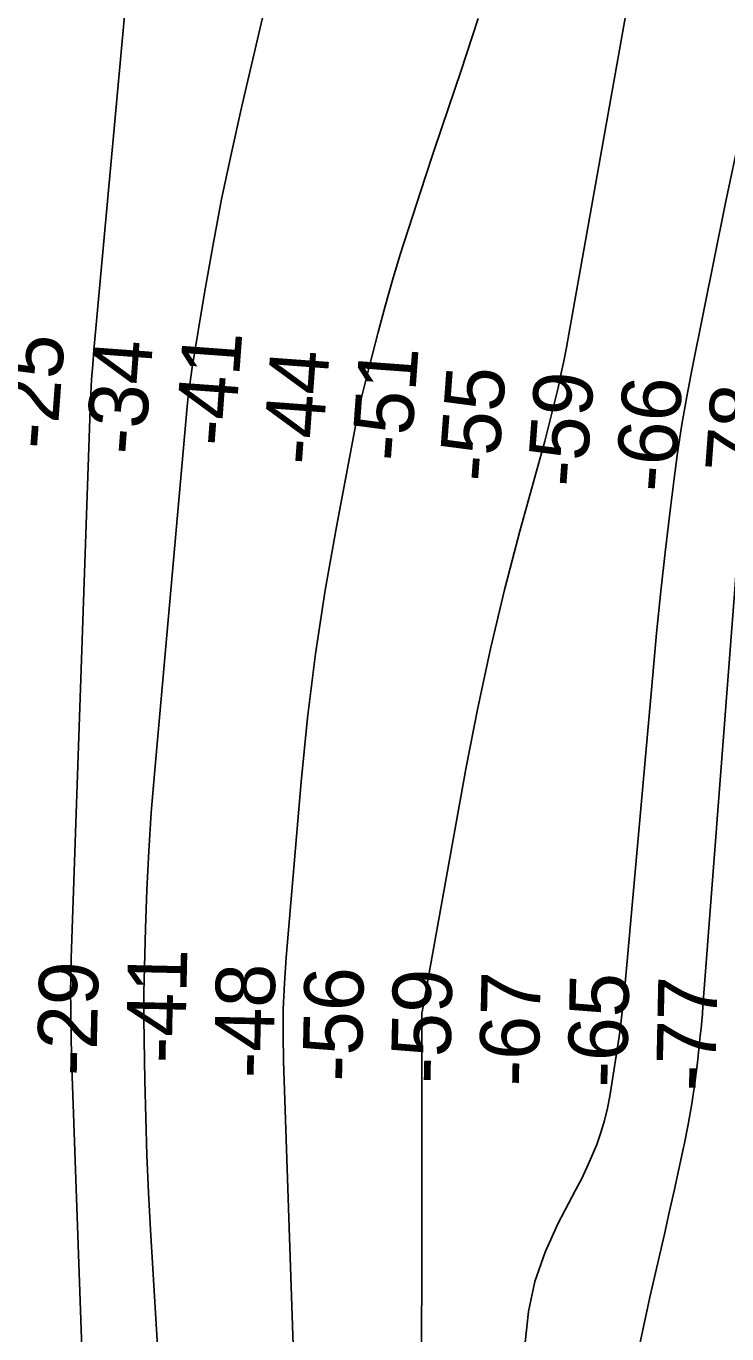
# Model space of a CAD drawing. Extents: x 3392644 to 3430565, y 576657 to 602123.
# Drawn here: x 3402367 to 3403159, y 590935 to 592413 of the extents above; entities that cross this region are included whole.
import ezdxf

# ---------------------------------------------------------------- set-up
doc = ezdxf.new("R2010")
doc.units = 0
for name, color, linetype in [('V-RIVR-EDGE', 7, 'Continuous'), ('V-RIVR-RANG', 7, 'Continuous'), ('V-TOPO-DPTH', 7, 'Continuous'), ('V-TOPO-MAJR', 7, 'Continuous'), ('V-TOPO-MINR', 7, 'Continuous')]:
    doc.layers.add(name, color=color, linetype=linetype)

msp = doc.modelspace()

# ---------------------------------------------------------------- linework, layer by layer
at = {"layer": 'V-RIVR-EDGE'}
msp.add_spline([(3402941, 594701.1), (3402930.8, 594681.4), (3402924.8, 594670.9), (3402918.4, 594656.4), (3402913.8, 594652.9), (3402910.3, 594649.7), (3402910, 594646.9), (3402909.9, 594643.4), (3402910.6, 594639.9), (3402906.1, 594637.8), (3402901.8, 594637.4), (3402902.5, 594630.7), (3402901.4, 594626.9), (3402898.3, 594620.2), (3402895.1, 594614.9), (3402892.3, 594612.4), (3402886.6, 594611), (3402883.1, 594607.5), (3402881, 594603.7), (3402879.9, 594598), (3402877, 594588.9), (3402875.6, 594583.9), (3402871, 594581.8), (3402867.5, 594579.4), (3402866.1, 594577.3), (3402866.1, 594575.5), (3402867.5, 594572), (3402865.7, 594571.6), (3402861.8, 594569.9), (3402860.4, 594565.7), (3402855.1, 594554.7), (3402849.5, 594546.7), (3402841, 594528.7), (3402832.8, 594515), (3402824, 594501.3), (3402815.1, 594486.1), (3402805.6, 594472.8), (3402801, 594465.4), (3402797.8, 594458.7), (3402795.3, 594450.9), (3402792.5, 594443.2), (3402788.9, 594435.8), (3402783.3, 594428.8), (3402777.3, 594426), (3402774.1, 594422.5), (3402768.1, 594411.5), (3402764.2, 594400.3), (3402763.4, 594393.6), (3402762, 594392.2), (3402754.6, 594393.6), (3402749.3, 594392.2), (3402746.5, 594387.6), (3402746.5, 594384.1), (3402747.9, 594382.3), (3402747.9, 594380.2), (3402745.4, 594380.2), (3402738.7, 594380.6), (3402736.6, 594376.7), (3402736.6, 594367.9), (3402735.9, 594363), (3402733.8, 594360.5), (3402727.8, 594357.4), (3402725.3, 594352.4), (3402723.2, 594346.5), (3402720, 594337.7), (3402712.5, 594321.1), (3402704, 594301.8), (3402700.8, 594294), (3402700.1, 594288.4), (3402702.6, 594283.1), (3402702.5, 594276), (3402700.4, 594269), (3402687.3, 594246.5), (3402678.5, 594232.8), (3402668.9, 594215.2), (3402660.4, 594200.7), (3402648.4, 594177.2), (3402635.7, 594158.9), (3402620.4, 594132.8), (3402617.3, 594129.7), (3402613, 594130.4), (3402610.2, 594129.3), (3402609.5, 594127.9), (3402609.5, 594126.5), (3402609.5, 594122.3), (3402607.4, 594121.6), (3402603.1, 594120.9), (3402602.1, 594117.7), (3402601.7, 594114.5), (3402607.7, 594111), (3402608.8, 594108.2), (3402605.9, 594108.2), (3402597.8, 594110), (3402594.3, 594102.9), (3402590.8, 594097.7), (3402590, 594094.5), (3402592.5, 594093.1), (3402593.2, 594090.6), (3402591.8, 594088.9), (3402589, 594087.1), (3402584.4, 594086.8), (3402582.3, 594086.1), (3402582.3, 594083.6), (3402582.3, 594081.8), (3402582.6, 594077.6), (3402582.2, 594074.8), (3402577.3, 594060.7), (3402570.5, 594046.3), (3402562.8, 594034.3), (3402557.1, 594026.9), (3402552.2, 594019.2), (3402547.6, 594010.4), (3402546.5, 594003.7), (3402544.4, 593999.1), (3402536.9, 593992.1), (3402524.9, 593978.4), (3402517.8, 593967.5), (3402508.3, 593951.3), (3402494.8, 593925.2), (3402486, 593905.2), (3402481.7, 593885.8), (3402481, 593873.1), (3402479.9, 593861.1), (3402477.4, 593860.4), (3402474.9, 593855.2), (3402471.7, 593845.7), (3402471, 593836.5), (3402466.8, 593828), (3402461.5, 593819.6), (3402459.3, 593812.2), (3402457.5, 593798.1), (3402452.9, 593789.7), (3402449, 593784.4), (3402445.8, 593778.4), (3402438.8, 593760.8), (3402434.5, 593749.5), (3402433.1, 593746.4), (3402433.1, 593738.3), (3402432.3, 593731.9), (3402430.2, 593728.8), (3402423.5, 593717.2), (3402419.6, 593715.1), (3402417.8, 593710.8), (3402417.5, 593707), (3402416.8, 593699.6), (3402415.7, 593692.2), (3402409.7, 593682), (3402400.5, 593663.7), (3402383.8, 593627.8), (3402369.6, 593595.4), (3402360.4, 593576), (3402343.4, 593537.6), (3402326.4, 593499.3), (3402307.6, 593441.5), (3402291.6, 593391.2), (3402279.9, 593360.6), (3402271, 593332.7), (3402263.9, 593311.3), (3402259.3, 593296.5), (3402256.5, 593293.3), (3402250.8, 593291.9), (3402249.1, 593287.3), (3402248.7, 593283.8), (3402247.3, 593275), (3402246.9, 593259.9), (3402245.8, 593251.4), (3402239.8, 593234.9), (3402233.7, 593219), (3402225.9, 593193.3), (3402216.7, 593160.6), (3402196.1, 593082.4), (3402192.9, 593072.5), (3402189.3, 593054.9), (3402186.4, 593042.2), (3402183.2, 593025), (3402180.4, 593014.1), (3402177.2, 593003.9), (3402173.3, 592988.4), (3402168.6, 592967.9), (3402164, 592947.5), (3402158.3, 592921.1), (3402152.3, 592901.7), (3402148.4, 592891.9), (3402148.3, 592886.9), (3402145.8, 592869.7), (3402139.8, 592830.6), (3402138.3, 592815.1), (3402134.7, 592799.9), (3402130.1, 592781.3), (3402123, 592752.4), (3402115.2, 592714), (3402112.3, 592697.1), (3402108, 592674.2), (3402103, 592647.8), (3402096.6, 592618.6), (3402093, 592606.2), (3402086.6, 592581.6), (3402081.7, 592565), (3402076.7, 592543.5), (3402073.8, 592527.7), (3402069.9, 592502.3), (3402067.7, 592482.3), (3402064.8, 592458), (3402064.4, 592437.9), (3402061.9, 592421.7), (3402056.6, 592389.6), (3402053.3, 592361.8), (3402051.9, 592338.5), (3402046.8, 592298.4), (3402043.6, 592273.4), (3402040.3, 592246.6), (3402037.9, 592234.6), (3402037.5, 592227.6), (3402036.4, 592217.3), (3402036.4, 592205.4), (3402034.6, 592188.1), (3402032, 592163.4), (3402027.7, 592136.3), (3402019.2, 592092.3), (3402019.2, 592082.8), (3402019.8, 592074.3), (3402019.8, 592070.4), (3402019.5, 592067.3), (3402015.6, 592056.7), (3402013.1, 592046.9), (3402009.5, 592028.9), (3402009.5, 592014.4), (3402009.1, 592004.2), (3402007, 591996.1), (3402003.8, 591983.8), (3402001.3, 591974.3), (3402000.2, 591956.3), (3402001.9, 591940.8), (3402003.3, 591932), (3402002.2, 591916.5), (3401998.6, 591888), (3401995.7, 591871.1), (3401991.4, 591845.7), (3401988.9, 591828.1), (3401987.9, 591815.4)], degree=3, dxfattribs=at)
at = {"layer": 'V-TOPO-DPTH'}
for points in [[(3402508.6, 592753.9), (3402443.8, 592047.2), (3402442.5, 592030.7), (3402441.3, 592014.2), (3402440.4, 591997.6), (3402439.7, 591981.1), (3402418.2, 591360.2), (3402418, 591351.5), (3402417.8, 591342.9), (3402417.7, 591334.2), (3402417.6, 591325.5), (3402417.6, 591316.9), (3402417.7, 591308.2), (3402417.7, 591299.5), (3402417.8, 591290.8), (3402418, 591281), (3402418.2, 591267.5), (3402418.5, 591253.9), (3402418.8, 591240.4), (3402419.3, 591226.8), (3402441.9, 590590.9)], [(3402441.9, 590590.9), (3402419.3, 591226.8), (3402418.8, 591240.4), (3402418.5, 591253.9), (3402418.2, 591267.5), (3402418, 591281), (3402417.8, 591290.8), (3402417.7, 591299.5), (3402417.7, 591308.2), (3402417.6, 591316.9), (3402417.6, 591325.5), (3402417.7, 591334.2), (3402417.8, 591342.9), (3402418, 591351.5), (3402418.2, 591360.2), (3402439.7, 591981.1), (3402440.4, 591997.6), (3402441.3, 592014.2), (3402442.5, 592030.7), (3402443.8, 592047.2), (3402508.6, 592753.9)], [(3402683.3, 592632.6), (3402611, 592322.9), (3402599.3, 592270.4), (3402588.2, 592217.8), (3402578.2, 592164.9), (3402568.9, 592111.9), (3402555, 592027.7), (3402553.3, 592016.7), (3402551.8, 592005.7), (3402550.5, 591994.7), (3402549.4, 591983.6), (3402512.3, 591568.2), (3402508.8, 591524.6), (3402505.9, 591481), (3402503.8, 591437.3), (3402502.3, 591393.6), (3402500.4, 591320.9), (3402500.3, 591313.5), (3402500.2, 591306.2), (3402500.2, 591298.9), (3402500.3, 591291.5), (3402501.5, 591221.8), (3402502.5, 591179.6), (3402503.8, 591137.4), (3402505.7, 591095.2), (3402507.9, 591053.1), (3402534.9, 590601.5)], [(3402683.3, 592632.6), (3402611, 592322.9), (3402599.3, 592270.4), (3402588.2, 592217.8), (3402578.2, 592164.9), (3402568.9, 592111.9), (3402555, 592027.7), (3402553.3, 592016.7), (3402551.8, 592005.7), (3402550.5, 591994.7), (3402549.4, 591983.6), (3402512.3, 591568.2), (3402508.8, 591524.6), (3402505.9, 591481), (3402503.8, 591437.3), (3402502.3, 591393.6), (3402500.4, 591320.9), (3402500.3, 591313.5), (3402500.2, 591306.2), (3402500.2, 591298.9), (3402500.3, 591291.5), (3402501.5, 591221.8), (3402502.5, 591179.6), (3402503.8, 591137.4), (3402505.7, 591095.2), (3402507.9, 591053.1), (3402534.9, 590601.5)]]:
    msp.add_lwpolyline(points, dxfattribs=at)
at = {"layer": 'V-TOPO-MAJR'}
msp.add_lwpolyline([(3402672.1, 590833.8), (3402658.2, 591244), (3402657.7, 591273.2), (3402657.9, 591302.4), (3402659.2, 591331.6), (3402661.2, 591360.7), (3402678.2, 591559.2), (3402685.5, 591631.7), (3402694.4, 591704), (3402705.4, 591775.9), (3402718, 591847.7), (3402740.1, 591963.7), (3402742.9, 591977.3), (3402745.8, 591990.8), (3402749, 592004.3), (3402752.3, 592017.8), (3402765.3, 592067.7), (3402773.2, 592097.1), (3402781.5, 592126.4), (3402790.3, 592155.5), (3402799.4, 592184.5), (3402808.8, 592213.4), (3402818.3, 592242.3), (3402828, 592271.2), (3402837.7, 592300.1), (3402858.7, 592362.1), (3402878.4, 592422.1)], dxfattribs=at)
at = {"layer": 'V-TOPO-MINR'}
for points in [[(3402508.6, 592753.9), (3402443.8, 592047.2), (3402442.5, 592030.7), (3402441.3, 592014.2), (3402440.4, 591997.6), (3402439.7, 591981.1), (3402418.2, 591360.2), (3402418, 591351.5), (3402417.8, 591342.9), (3402417.7, 591334.2), (3402417.6, 591325.5), (3402417.6, 591316.9), (3402417.7, 591308.2), (3402417.7, 591299.5), (3402417.8, 591290.8), (3402418, 591281), (3402418.2, 591267.5), (3402418.5, 591253.9), (3402418.8, 591240.4), (3402419.3, 591226.8), (3402441.9, 590590.9)], [(3403099.2, 592729.7), (3402980.9, 592065.5), (3402978.1, 592050.2), (3402975.1, 592035), (3402971.9, 592019.8), (3402968.6, 592004.7), (3402965.1, 591989.6), (3402961.4, 591974.5), (3402957.5, 591959.5), (3402953.5, 591944.5), (3402925.5, 591842.5), (3402908.2, 591776.3), (3402892.1, 591709.8), (3402877.9, 591643), (3402864.8, 591575.8), (3402814.9, 591299.2), (3402814.8, 591298.9), (3402814.8, 591298.3), (3402814.7, 591297.1), (3402814.7, 591296.8), (3402814.4, 590636.9)], [(3402534.9, 590601.5), (3402507.9, 591053.1), (3402505.7, 591095.2), (3402503.8, 591137.4), (3402502.5, 591179.6), (3402501.5, 591221.8), (3402500.3, 591291.5), (3402500.2, 591298.9), (3402500.2, 591306.2), (3402500.3, 591313.5), (3402500.4, 591320.9), (3402502.3, 591393.6), (3402503.8, 591437.3), (3402505.9, 591481), (3402508.8, 591524.6), (3402512.3, 591568.2), (3402549.4, 591983.6), (3402550.5, 591994.7), (3402551.8, 592005.7), (3402553.3, 592016.7), (3402555, 592027.7), (3402568.9, 592111.9), (3402578.2, 592164.9), (3402588.2, 592217.8), (3402599.3, 592270.4), (3402611, 592322.9), (3402683.3, 592632.6)], [(3403174.8, 592293.8), (3403157.8, 592213.7), (3403120.2, 592026.6), (3403114.2, 591994.9), (3403108.6, 591963.1), (3403103.8, 591931.2), (3403099.5, 591899.3), (3403095.8, 591869.1), (3403090.1, 591821.9), (3403084.9, 591774.8), (3403080.1, 591727.5), (3403075.6, 591680.3), (3403043.3, 591318.9), (3403042, 591305.7), (3403040.5, 591292.6), (3403038.8, 591279.4), (3403036.9, 591266.4), (3403027.1, 591204.2), (3403024.5, 591190.3), (3403021.2, 591176.5), (3403017, 591162.9), (3403012.3, 591149.5), (3403006.9, 591136.3), (3403001.1, 591123.3), (3402995, 591110.4), (3402988.5, 591097.7), (3402968.4, 591059.9), (3402954, 591027.7), (3402942.5, 590994.7), (3402935.4, 590960.5), (3402931.3, 590925.5)], [(3403173.8, 591845.9), (3403132.5, 591305.6), (3403131.9, 591297.2), (3403131.1, 591288.9), (3403130.3, 591280.5), (3403129.4, 591272.1), (3403126.2, 591242), (3403123.2, 591218.6), (3403119.8, 591195.3), (3403115.7, 591172.1), (3403111.2, 591148.9), (3403110.5, 591146), (3403105.2, 591121.5), (3403099.8, 591097), (3403094.3, 591072.5), (3403088.8, 591048), (3403072.4, 590976.9), (3403059.5, 590916.8)]]:
    msp.add_lwpolyline(points, dxfattribs=at)

# ---------------------------------------------------------------- texts
at = {"layer": 'V-RIVR-RANG'}
for s, rotation, p in [('-25', 85.7784, (3402401.4, 591933.9)), ('-34', 85.7784, (3402501.2, 591927.6)), ('-41', 85.7784, (3402602.2, 591937.4)), ('-44', 85.7784, (3402700.9, 591916.1)), ('-51', 85.7784, (3402801.5, 591920.1)), ('-55', 85.7784, (3402900.1, 591897)), ('-59', 85.7784, (3402999.9, 591891.2)), ('-66', 85.7784, (3403099.7, 591885.4)), ('-78', 85.7784, (3403199.4, 591876.8)), ('-41', 88.7658, (3402546.8, 591240.8)), ('-29', 88.7658, (3402446.5, 591226.3)), ('-48', 88.7658, (3402646.4, 591223.9)), ('-56', 88.7658, (3402746.4, 591219.9)), ('-59', 88.7658, (3402846.4, 591217.8)), ('-67', 88.7658, (3402946.3, 591214.6)), ('-65', 88.7658, (3403046.3, 591213.2)), ('-77', 88.7658, (3403146.2, 591209.2))]:
    msp.add_text(s, height=67, rotation=rotation, dxfattribs=at).set_placement(p)

doc.saveas('drawing.dxf')
